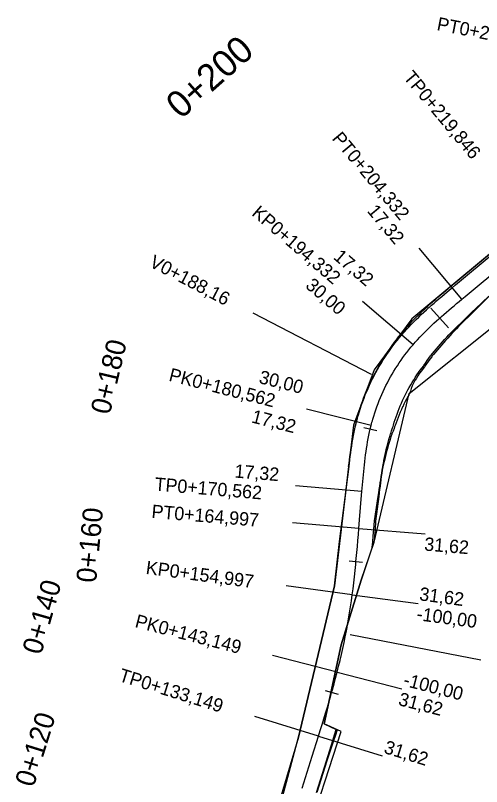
# Model space of a CAD drawing. Extents: x -636600 to -628587, y -1090963 to -1085869.
# Drawn here: x -635542.6 to -635472.6, y -1089372.4 to -1089256.7 of the extents above; entities that cross this region are included whole.
import ezdxf

# ---------------------------------------------------------------- set-up
doc = ezdxf.new("R2010")
doc.units = 0
for name, color, linetype in [('01_PARCELY_NÁVRH_PC', 7, 'Continuous'), ('HEKTOMETRY100', 7, 'Continuous'), ('HEKTOMETRY20', 7, 'Continuous'), ('HL_BODY', 7, 'Continuous'), ('POLOMERY', 7, 'Continuous'), ('situace_osa', 7, 'Continuous'), ('situace_těleso', 7, 'Continuous'), ('situace_vozovka', 7, 'Continuous'), ('VRCHOLY', 7, 'Continuous')]:
    doc.layers.add(name, color=color, linetype=linetype)

msp = doc.modelspace()

# ---------------------------------------------------------------- linework, layer by layer
at = {"layer": '01_PARCELY_NÁVRH_PC'}
for points in [[(-635443.44, -1089224.63), (-635451.92, -1089265.39), (-635454.78, -1089273.56), (-635459.41, -1089281.14), (-635466.37, -1089288.27), (-635483.11, -1089302.2), (-635488.77, -1089309.88), (-635491.85, -1089318.15), (-635494.73, -1089342.26), (-635500.09, -1089364.95), (-635508.38, -1089392.72)], [(-635504.63, -1089397.71), (-635493.73, -1089364.12), (-635496.25, -1089362.96), (-635493.69, -1089351.13), (-635490.7, -1089341.4), (-635488.78, -1089335.72), (-635483.51, -1089313.39), (-635469.84, -1089302.51), (-635459.93, -1089296.4), (-635445.43, -1089276.75), (-635446.89, -1089270.21), (-635442.08, -1089243.47)]]:
    msp.add_lwpolyline(points, dxfattribs=at)
at = {"layer": 'HEKTOMETRY100'}
msp.add_lwpolyline([(-635480.25, -1089300.59), (-635477.59, -1089303.58)], dxfattribs=at)
at = {"layer": 'HEKTOMETRY20'}
for points in [[(-635490.32, -1089318.52), (-635488.38, -1089318.98)], [(-635492.49, -1089338.53), (-635490.49, -1089338.72)], [(-635496.1, -1089357.98), (-635494.17, -1089358.53)]]:
    msp.add_lwpolyline(points, dxfattribs=at)
at = {"layer": 'HL_BODY'}
for points in [[(-635475.63, -1089299.28), (-635482.03, -1089291.6)], [(-635482.93, -1089306.09), (-635490.52, -1089299.59)], [(-635489.22, -1089318.21), (-635498.91, -1089315.74)], [(-635490.6, -1089328.1), (-635500.56, -1089327.27)], [(-635491.06, -1089333.64), (-635501.02, -1089332.82)], [(-635492.05, -1089343.59), (-635501.96, -1089342.27)], [(-635494.31, -1089355.22), (-635504, -1089352.73)], [(-635497.12, -1089364.81), (-635506.67, -1089361.85)]]:
    msp.add_lwpolyline(points, dxfattribs=at)
at = {"layer": 'POLOMERY'}
for points in [[(-635475.63, -1089299.28), (-635482.03, -1089291.6)], [(-635482.93, -1089306.09), (-635490.52, -1089299.59)], [(-635489.22, -1089318.21), (-635498.91, -1089315.74)], [(-635490.6, -1089328.1), (-635500.56, -1089327.27)], [(-635491.06, -1089333.64), (-635481.09, -1089334.47)], [(-635492.05, -1089343.59), (-635482.14, -1089344.92)], [(-635494.31, -1089355.22), (-635484.62, -1089357.7)], [(-635497.12, -1089364.81), (-635487.57, -1089367.78)]]:
    msp.add_lwpolyline(points, dxfattribs=at)
at = {"layer": 'situace_osa'}
msp.add_lwpolyline([(-635499.54, -1089372.6), (-635498.05, -1089367.82), (-635497.12, -1089364.81), (-635496.85, -1089363.95), (-635496.58, -1089363.08), (-635496.57, -1089363.05), (-635496.31, -1089362.21), (-635496.05, -1089361.34), (-635495.78, -1089360.47), (-635495.52, -1089359.6), (-635495.27, -1089358.72), (-635495.14, -1089358.26), (-635495.02, -1089357.85), (-635494.78, -1089356.97), (-635494.54, -1089356.1), (-635494.31, -1089355.22), (-635494.09, -1089354.33), (-635493.87, -1089353.45), (-635493.87, -1089353.42), (-635493.67, -1089352.56), (-635493.47, -1089351.67), (-635493.28, -1089350.78), (-635493.1, -1089349.89), (-635492.92, -1089348.99), (-635492.83, -1089348.53), (-635492.76, -1089348.1), (-635492.6, -1089347.2), (-635492.45, -1089346.3), (-635492.31, -1089345.4), (-635492.17, -1089344.5), (-635492.05, -1089343.59), (-635492.05, -1089343.59), (-635491.93, -1089342.69), (-635491.82, -1089341.79), (-635491.72, -1089340.89), (-635491.63, -1089339.98), (-635491.53, -1089339.08), (-635491.49, -1089338.62), (-635491.45, -1089338.17), (-635491.36, -1089337.27), (-635491.28, -1089336.36), (-635491.21, -1089335.46), (-635491.13, -1089334.55), (-635491.06, -1089333.64), (-635491.06, -1089333.64), (-635490.95, -1089332.35), (-635490.64, -1089328.66), (-635490.6, -1089328.1), (-635490.55, -1089327.6), (-635490.51, -1089327.1), (-635490.47, -1089326.6), (-635490.43, -1089326.11), (-635490.38, -1089325.61), (-635490.33, -1089325.11), (-635490.28, -1089324.61), (-635490.23, -1089324.12), (-635490.18, -1089323.68), (-635490.17, -1089323.62), (-635490.11, -1089323.12), (-635490.05, -1089322.63), (-635489.98, -1089322.13), (-635489.91, -1089321.64), (-635489.83, -1089321.14), (-635489.74, -1089320.65), (-635489.65, -1089320.16), (-635489.55, -1089319.67), (-635489.45, -1089319.18), (-635489.35, -1089318.75), (-635489.34, -1089318.69), (-635489.22, -1089318.21), (-635489.09, -1089317.73), (-635489.03, -1089317.49), (-635488.96, -1089317.26), (-635488.82, -1089316.79), (-635488.67, -1089316.32), (-635488.51, -1089315.85), (-635488.35, -1089315.39), (-635488.18, -1089314.93), (-635488, -1089314.47), (-635487.81, -1089314.01), (-635487.81, -1089314), (-635487.62, -1089313.56), (-635487.42, -1089313.11), (-635487.21, -1089312.67), (-635486.99, -1089312.23), (-635486.77, -1089311.79), (-635486.54, -1089311.35), (-635486.3, -1089310.92), (-635486.06, -1089310.5), (-635485.81, -1089310.07), (-635485.55, -1089309.65), (-635485.5, -1089309.57), (-635485.28, -1089309.24), (-635485.01, -1089308.83), (-635484.73, -1089308.42), (-635484.45, -1089308.02), (-635484.16, -1089307.63), (-635483.93, -1089307.33), (-635483.86, -1089307.24), (-635483.55, -1089306.85), (-635483.24, -1089306.47), (-635482.93, -1089306.09), (-635482.6, -1089305.72), (-635482.49, -1089305.59), (-635482.26, -1089305.34), (-635481.92, -1089304.98), (-635481.58, -1089304.62), (-635481.23, -1089304.26), (-635480.87, -1089303.91), (-635480.52, -1089303.56), (-635480.15, -1089303.21), (-635479.79, -1089302.87), (-635479.42, -1089302.53), (-635479.05, -1089302.2), (-635478.92, -1089302.09), (-635478.67, -1089301.87), (-635478.3, -1089301.54), (-635477.92, -1089301.21), (-635477.54, -1089300.89), (-635477.16, -1089300.56), (-635476.78, -1089300.24), (-635476.39, -1089299.92), (-635476.01, -1089299.6), (-635475.63, -1089299.28), (-635475.11, -1089298.85), (-635473.01, -1089297.1), (-635471.27, -1089295.64)], dxfattribs=at)
at = {"layer": 'situace_těleso'}
for points in [[(-635492.59, -1089324.37), (-635492.53, -1089323.86), (-635492.47, -1089323.41), (-635492.46, -1089323.35), (-635492.39, -1089322.84), (-635492.32, -1089322.32), (-635492.24, -1089321.81), (-635492.16, -1089321.29), (-635492.07, -1089320.77), (-635491.98, -1089320.25), (-635491.88, -1089319.73), (-635491.78, -1089319.21), (-635491.66, -1089318.69), (-635491.56, -1089318.23), (-635491.54, -1089318.17), (-635491.4, -1089317.65), (-635491.27, -1089317.14), (-635491.21, -1089316.88), (-635491.14, -1089316.62), (-635491, -1089316.11), (-635490.85, -1089315.61), (-635490.69, -1089315.1), (-635490.52, -1089314.6), (-635490.34, -1089314.1), (-635490.15, -1089313.61), (-635489.96, -1089313.11), (-635489.95, -1089313.1), (-635489.75, -1089312.63), (-635489.53, -1089312.14), (-635489.31, -1089311.66), (-635489.08, -1089311.19), (-635488.83, -1089310.72), (-635488.58, -1089310.25), (-635488.32, -1089309.79), (-635488.05, -1089309.33), (-635487.75, -1089308.9), (-635487.47, -1089308.45), (-635487.42, -1089308.36), (-635487.22, -1089307.98), (-635486.94, -1089307.53), (-635486.65, -1089307.08), (-635486.36, -1089306.64), (-635486.06, -1089306.2), (-635485.82, -1089305.88), (-635485.75, -1089305.77), (-635485.43, -1089305.35), (-635485.11, -1089304.93), (-635484.77, -1089304.51), (-635484.43, -1089304.09), (-635484.31, -1089303.96), (-635484.08, -1089303.69), (-635483.72, -1089303.29), (-635483.36, -1089302.89), (-635482.99, -1089302.51), (-635482.62, -1089302.13), (-635482.25, -1089301.76), (-635481.87, -1089301.39), (-635481.49, -1089301.03), (-635481.11, -1089300.67), (-635480.72, -1089300.32), (-635480.6, -1089300.21), (-635480.34, -1089299.97), (-635479.96, -1089299.63), (-635479.57, -1089299.29), (-635479.19, -1089298.95), (-635478.8, -1089298.62), (-635478.41, -1089298.29), (-635478.03, -1089297.97), (-635477.64, -1089297.65), (-635477.25, -1089297.33), (-635476.74, -1089296.9), (-635474.64, -1089295.15), (-635472.9, -1089293.7), (-635469.05, -1089290.5)], [(-635471.54, -1089298.87), (-635473.49, -1089300.79), (-635473.97, -1089301.26), (-635474.33, -1089301.61), (-635474.68, -1089301.96), (-635475.05, -1089302.29), (-635475.4, -1089302.64), (-635475.75, -1089302.99), (-635476.09, -1089303.34), (-635476.43, -1089303.69), (-635476.76, -1089304.04), (-635476.98, -1089304.27), (-635477.09, -1089304.39), (-635477.42, -1089304.74), (-635477.73, -1089305.1), (-635478.04, -1089305.45), (-635478.35, -1089305.81), (-635478.65, -1089306.17), (-635478.96, -1089306.51), (-635479.26, -1089306.85), (-635479.56, -1089307.2), (-635479.85, -1089307.55), (-635480.04, -1089307.78), (-635480.13, -1089307.9), (-635480.4, -1089308.26), (-635480.66, -1089308.61), (-635480.91, -1089308.97), (-635481.16, -1089309.33), (-635481.22, -1089309.42), (-635481.42, -1089309.68), (-635481.68, -1089310.03), (-635481.94, -1089310.38), (-635482.19, -1089310.74), (-635482.43, -1089311.1), (-635482.62, -1089311.39), (-635482.67, -1089311.47), (-635482.88, -1089311.84), (-635483.04, -1089312.26), (-635483.19, -1089312.67), (-635483.33, -1089313.08), (-635483.42, -1089313.32), (-635483.51, -1089313.39), (-635483.57, -1089313.66), (-635483.69, -1089313.87), (-635483.9, -1089314.25), (-635484.1, -1089314.63), (-635484.3, -1089315.02), (-635484.48, -1089315.4), (-635484.49, -1089315.41), (-635484.67, -1089315.8), (-635484.85, -1089316.2), (-635485.01, -1089316.6), (-635485.18, -1089317), (-635485.33, -1089317.41), (-635485.48, -1089317.81), (-635485.62, -1089318.23), (-635485.69, -1089318.43), (-635485.77, -1089318.64), (-635485.93, -1089319.04), (-635486.09, -1089319.46), (-635486.11, -1089319.52), (-635486.24, -1089319.89), (-635486.38, -1089320.32), (-635486.52, -1089320.76), (-635486.65, -1089321.2), (-635486.78, -1089321.65), (-635486.9, -1089322.1), (-635487.01, -1089322.56), (-635487.13, -1089323.02), (-635487.23, -1089323.48), (-635487.34, -1089323.95), (-635487.35, -1089324.01), (-635487.44, -1089324.42), (-635487.54, -1089324.9), (-635487.62, -1089325.38), (-635487.69, -1089325.86), (-635487.75, -1089326.35), (-635487.82, -1089326.83), (-635487.88, -1089327.33), (-635487.94, -1089327.82), (-635488.01, -1089328.31), (-635488.08, -1089328.87), (-635488.54, -1089332.55), (-635488.63, -1089333.84), (-635488.63, -1089333.85), (-635488.69, -1089334.75), (-635488.75, -1089335.57)], [(-635492.59, -1089324.37), (-635494.73, -1089342.26), (-635500.09, -1089364.95), (-635504.25, -1089378.89)], [(-635494.33, -1089363.85), (-635496.25, -1089362.96), (-635493.69, -1089351.13), (-635490.7, -1089341.4), (-635488.78, -1089335.72), (-635488.75, -1089335.57)], [(-635494.33, -1089363.85), (-635494.58, -1089364.65), (-635494.86, -1089365.52), (-635495.84, -1089368.51), (-635497.37, -1089373.27)]]:
    msp.add_lwpolyline(points, dxfattribs=at)
at = {"layer": 'situace_vozovka'}
for points in [[(-635492.52, -1089324.38), (-635492.47, -1089323.87), (-635492.41, -1089323.42), (-635492.41, -1089323.36), (-635492.34, -1089322.84), (-635492.28, -1089322.33), (-635492.21, -1089321.81), (-635492.13, -1089321.29), (-635492.05, -1089320.77), (-635491.96, -1089320.26), (-635491.86, -1089319.73), (-635491.76, -1089319.21), (-635491.65, -1089318.69), (-635491.54, -1089318.24), (-635491.53, -1089318.17), (-635491.4, -1089317.65), (-635491.26, -1089317.14), (-635491.19, -1089316.88), (-635491.12, -1089316.63), (-635490.97, -1089316.12), (-635490.81, -1089315.62), (-635490.64, -1089315.12), (-635490.46, -1089314.62), (-635490.28, -1089314.13), (-635490.09, -1089313.63), (-635489.89, -1089313.14), (-635489.88, -1089313.13), (-635489.68, -1089312.66), (-635489.46, -1089312.18), (-635489.24, -1089311.7), (-635489.01, -1089311.22), (-635488.77, -1089310.75), (-635488.52, -1089310.28), (-635488.26, -1089309.82), (-635488, -1089309.36), (-635487.73, -1089308.91), (-635487.45, -1089308.46), (-635487.4, -1089308.37), (-635487.17, -1089308.01), (-635486.88, -1089307.57), (-635486.58, -1089307.14), (-635486.27, -1089306.7), (-635485.96, -1089306.28), (-635485.72, -1089305.96), (-635485.64, -1089305.86), (-635485.31, -1089305.44), (-635484.98, -1089305.03), (-635484.63, -1089304.63), (-635484.28, -1089304.23), (-635484.16, -1089304.09), (-635483.92, -1089303.83), (-635483.56, -1089303.44), (-635483.2, -1089303.05), (-635482.83, -1089302.67), (-635482.45, -1089302.3), (-635482.08, -1089301.94), (-635481.7, -1089301.58), (-635481.32, -1089301.22), (-635480.93, -1089300.87), (-635480.55, -1089300.52), (-635480.42, -1089300.41), (-635480.16, -1089300.18), (-635479.77, -1089299.84), (-635479.39, -1089299.51), (-635479, -1089299.17), (-635478.61, -1089298.84), (-635478.22, -1089298.52), (-635477.84, -1089298.19), (-635477.45, -1089297.87), (-635477.07, -1089297.55), (-635476.56, -1089297.12), (-635474.46, -1089295.37), (-635472.72, -1089293.92), (-635468.88, -1089290.71)], [(-635489.04, -1089336.48), (-635488.97, -1089335.65), (-635488.89, -1089334.74), (-635488.81, -1089333.83), (-635488.81, -1089333.83), (-635488.71, -1089332.53), (-635488.16, -1089328.86), (-635488.08, -1089328.31), (-635488, -1089327.81), (-635487.93, -1089327.32), (-635487.86, -1089326.83), (-635487.78, -1089326.34), (-635487.7, -1089325.86), (-635487.63, -1089325.38), (-635487.54, -1089324.9), (-635487.46, -1089324.42), (-635487.39, -1089324), (-635487.37, -1089323.95), (-635487.29, -1089323.48), (-635487.19, -1089323.01), (-635487.1, -1089322.55), (-635486.99, -1089322.09), (-635486.89, -1089321.63), (-635486.78, -1089321.18), (-635486.66, -1089320.73), (-635486.54, -1089320.29), (-635486.41, -1089319.85), (-635486.3, -1089319.47), (-635486.28, -1089319.42), (-635486.14, -1089318.99), (-635486, -1089318.57), (-635485.93, -1089318.37), (-635485.87, -1089318.15), (-635485.74, -1089317.73), (-635485.61, -1089317.32), (-635485.47, -1089316.9), (-635485.32, -1089316.49), (-635485.17, -1089316.07), (-635485.01, -1089315.67), (-635484.84, -1089315.26), (-635484.84, -1089315.25), (-635484.67, -1089314.86), (-635484.49, -1089314.45), (-635484.3, -1089314.06), (-635484.11, -1089313.66), (-635483.91, -1089313.27), (-635483.71, -1089312.88), (-635483.49, -1089312.5), (-635483.28, -1089312.12), (-635483.05, -1089311.74), (-635482.82, -1089311.37), (-635482.78, -1089311.3), (-635482.59, -1089311), (-635482.34, -1089310.63), (-635482.09, -1089310.27), (-635481.84, -1089309.91), (-635481.58, -1089309.56), (-635481.38, -1089309.3), (-635481.32, -1089309.2), (-635481.07, -1089308.84), (-635480.82, -1089308.48), (-635480.56, -1089308.12), (-635480.29, -1089307.76), (-635480.2, -1089307.64), (-635480.01, -1089307.4), (-635479.72, -1089307.05), (-635479.43, -1089306.69), (-635479.13, -1089306.34), (-635478.82, -1089305.99), (-635478.51, -1089305.64), (-635478.19, -1089305.29), (-635477.87, -1089304.95), (-635477.54, -1089304.6), (-635477.21, -1089304.26), (-635477.09, -1089304.14), (-635476.87, -1089303.92), (-635476.53, -1089303.57), (-635476.18, -1089303.23), (-635475.83, -1089302.89), (-635475.48, -1089302.55), (-635475.12, -1089302.2), (-635474.77, -1089301.86), (-635474.41, -1089301.52), (-635474.04, -1089301.17), (-635473.56, -1089300.71), (-635471.57, -1089298.82)], [(-635503.88, -1089378.99), (-635500.09, -1089364.95), (-635494.73, -1089342.26), (-635493.94, -1089335.62), (-635492.52, -1089324.38)], [(-635489.04, -1089336.48), (-635490.7, -1089341.4), (-635493.69, -1089351.13), (-635496.25, -1089362.96), (-635494.44, -1089363.79)], [(-635497.39, -1089373.26), (-635495.9, -1089368.49), (-635494.97, -1089365.48), (-635494.7, -1089364.61), (-635494.44, -1089363.79)]]:
    msp.add_lwpolyline(points, dxfattribs=at)
at = {"layer": 'VRCHOLY'}
for points in [[(-635489.14, -1089310.56), (-635506.89, -1089301.34)], [(-635492.38, -1089349.56), (-635472.75, -1089353.38)]]:
    msp.add_lwpolyline(points, dxfattribs=at)

# ---------------------------------------------------------------- texts
at = {"layer": 'HEKTOMETRY100'}
msp.add_text('0+200', height=4, rotation=41.6476, dxfattribs=at).set_placement((-635517.75, -1089272.38))
at = {"layer": 'HEKTOMETRY20'}
for s, rotation, p in [('0+180', 76.7462, (-635528.42, -1089316.7)), ('0+160', 84.5373, (-635530.48, -1089341.88)), ('0+140', 74.0793, (-635538.72, -1089352.73)), ('0+120', 72.7345, (-635539.85, -1089372.59))]:
    msp.add_text(s, height=3, rotation=rotation, dxfattribs=at).set_placement(p)
at = {"layer": 'HL_BODY'}
for s, rotation, p in [('PT0+250,352', 349.019, (-635479.46, -1089258.88)), ('TP0+219,846', 309.8559, (-635484.47, -1089266.04)), ('PT0+204,332', 309.8559, (-635495.18, -1089275.2)), ('KP0+194,332', 319.4052, (-635507.25, -1089286.56)), ('PK0+180,562', 345.7032, (-635519.68, -1089311.48)), ('TP0+170,562', 355.2525, (-635521.75, -1089327.97)), ('PT0+164,997', 355.2525, (-635522.21, -1089332.06)), ('KP0+154,997', 352.3877, (-635523.09, -1089340.46)), ('PK0+143,149', 345.5993, (-635524.76, -1089348.43)), ('TP0+133,149', 342.7345, (-635527.19, -1089356.51))]:
    msp.add_text(s, height=2, rotation=rotation, dxfattribs=at).set_placement(p)
at = {"layer": 'POLOMERY'}
for s, rotation, p in [('17,32', 309.8559, (-635489.9, -1089286.08)), ('17,32', 319.4052, (-635495, -1089293.11)), ('30,00', 319.4052, (-635499.2, -1089297.42)), ('30,00', 345.7032, (-635506.17, -1089311.82)), ('17,32', 345.7032, (-635507.28, -1089317.73)), ('17,32', 355.2525, (-635509.76, -1089326.01)), ('31,62', 355.2525, (-635481.3, -1089336.96)), ('31,62', 352.3877, (-635482.07, -1089344.42)), ('-100,00', 352.3877, (-635482.47, -1089347.4)), ('-100,00', 345.5993, (-635484.5, -1089357.22)), ('31,62', 345.5993, (-635485.25, -1089360.13)), ('31,62', 342.7345, (-635487.42, -1089367.3))]:
    msp.add_text(s, height=2, rotation=rotation, dxfattribs=at).set_placement(p)
at = {"layer": 'VRCHOLY'}
msp.add_text('V0+188,16', height=2, rotation=332.5542, dxfattribs=at).set_placement((-635522.62, -1089294.29))

doc.saveas('drawing.dxf')
